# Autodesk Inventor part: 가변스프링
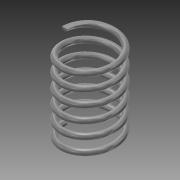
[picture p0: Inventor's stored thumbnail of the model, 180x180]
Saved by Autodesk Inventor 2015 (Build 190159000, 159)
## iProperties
Created: 2015-10
Part Number: 가변스프링
Material: Steel, Mild
Document SubType Name: Modeling
Designer: youjin09
Mass: 128.864 g
Surface Area: 133.03 cm^2
Volume: 16.4159 cm^3
Density: 7.85 g/cm^3
Appearance: Semi-Polished
Author: youjin09
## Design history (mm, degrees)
sketch "Sketch2"
  geometry: L1 (0, 0)-(22.5, 0); L2 (22.5, 0)-(22.5, 73.25); L3 (22.5, 73.25)-(0, 73.25); L4 (0, 73.25)-(0, 0); C1 r 2.5 at (22.5, 0)
  constraints: 8 end point, 2 parallel, 1 centre point, 1 coincident, 1 horizontal, 1 perpendicular
  dimensions: "d0" = 73.25 distance of L3.end L1.start (derived); "d1" = 45 diameter of L2 L4; "d2" = 5 diameter of C1
coil "Coil1" pitch "d3" = 10; turns "d5" = 6; dims "d4" = 73.25 (= d0), "d6" = 0, angle "d7" = 90 deg, angle "d8" = 90 deg, "d9" = 0, "d10" = 0
workplane "Work Plane1"
sketch "Sketch3"
  geometry: L1 (20, 0)-(25, 0) reference; 1 further point
  constraints: 1 horizontal alignment
extrude "Extrusion1" cut sketch "Sketch3" stored distance "d11" = 10; taper "d12" = 0 deg
workplane "Work Plane2"
sketch "Sketch4"
  geometry: L1 (25, 0)-(20, 0) reference; 1 further point
  constraints: 1 horizontal alignment
extrude "Extrusion2" cut sketch "Sketch4" stored distance "d13" = 10; taper "d14" = 0 deg
body "Solid1"
node "Project Cut Edges1"
node "Project Cut Edges2"
